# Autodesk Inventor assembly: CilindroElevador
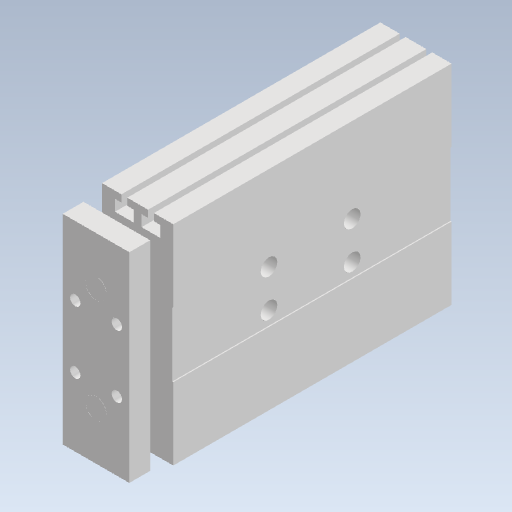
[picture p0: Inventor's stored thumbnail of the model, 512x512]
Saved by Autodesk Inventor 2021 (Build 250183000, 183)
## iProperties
Created: 2021-02
Part Number: CilindroElevador
Document SubType Name: Assembly
Designer: ATOUZA
Author: ATOUZA
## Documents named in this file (4)
- D:\01 Paralaia\Grupos de Traballo\GT Maquetas\CAD 3D\E_Medida\CilindroElevador\CilindroElevador.iam
- D:\01 Paralaia\Grupos de Traballo\GT Maquetas\CAD 3D\E_Medida\CilindroElevador\CuerpoCilindro.ipt
- D:\01 Paralaia\Grupos de Traballo\GT Maquetas\CAD 3D\E_Medida\CilindroElevador\vástago.ipt
- D:\01 Paralaia\Grupos de Traballo\GT Maquetas\CAD 3D\E_Medida\CilindroElevador\SoporteSuperior.ipt
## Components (4 placed, 3 different names)
1. CuerpoCilindro:1 — Insertar:1, Insertar:2, Ángulo:1
2. vástago:1 — Insertar:1, Nivelación:1, Coincidencia:2
3. vástago:2 — Insertar:2, Nivelación:1, Coincidencia:1
4. SoporteSuperior:1 — Coincidencia:1, Coincidencia:2, Ángulo:1
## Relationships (6: Insert 2, Mate 2, Flush 1, Angle 1)
- Insertar:1: CuerpoCilindro:1 ↔ vástago:1
- Insertar:2: CuerpoCilindro:1 ↔ vástago:2
- Nivelación:1 [Flush]: vástago:1 ↔ vástago:2
- Coincidencia:1 [Mate]: vástago:2 ↔ SoporteSuperior:1
- Coincidencia:2 [Mate]: vástago:1 ↔ SoporteSuperior:1
- Ángulo:1 [Angle]: CuerpoCilindro:1 ↔ SoporteSuperior:1
